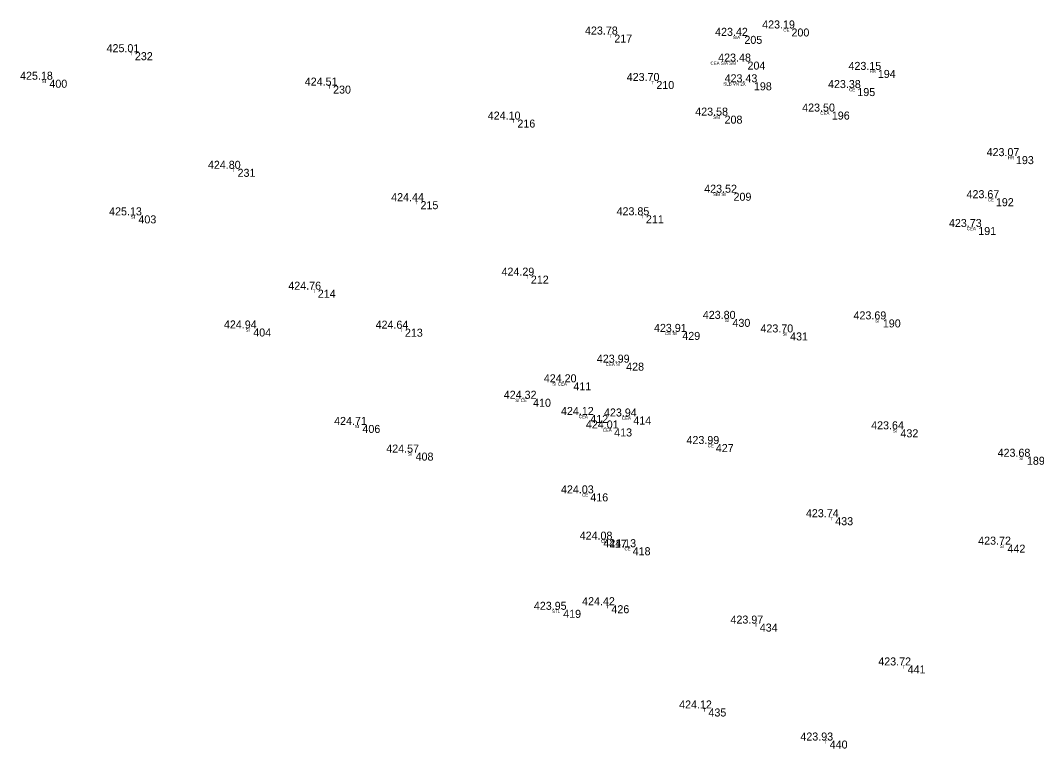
# Model space of a CAD drawing. Extents: x -639373 to -639057, y -1138651 to -1138359.
# Drawn here: x -639278.6 to -639183.3, y -1138568.9 to -1138500.7 of the extents above; entities that cross this region are included whole.
import ezdxf

# ---------------------------------------------------------------- set-up
doc = ezdxf.new("R2010")
doc.units = 0
for name, color, linetype in [('Vrstva 11', 7, 'Continuous'), ('Vrstva 13', 7, 'Continuous'), ('Vrstva 14', 7, 'Continuous'), ('Vrstva 57', 7, 'Continuous')]:
    doc.layers.add(name, color=color, linetype=linetype)

msp = doc.modelspace()

# ---------------------------------------------------------------- linework, layer by layer
at = {"layer": 'Vrstva 11'}
for p, q in [((-639223.19, -1138502.05), (-639223.19, -1138502.05)), ((-639211, -1138502.17), (-639211, -1138502.17)), ((-639206.59, -1138501.48), (-639206.59, -1138501.48)), ((-639268.11, -1138503.7), (-639268.11, -1138503.7)), ((-639210.71, -1138504.58), (-639210.71, -1138504.58)), ((-639198.5, -1138505.36), (-639198.5, -1138505.36)), ((-639276.12, -1138506.28), (-639276.12, -1138506.28)), ((-639249.54, -1138506.83), (-639249.54, -1138506.83)), ((-639219.25, -1138506.4), (-639219.25, -1138506.4)), ((-639210.11, -1138506.52), (-639210.11, -1138506.52)), ((-639200.42, -1138507.06), (-639200.42, -1138507.06)), ((-639232.27, -1138510.01), (-639232.27, -1138510.01)), ((-639212.86, -1138509.64), (-639212.86, -1138509.64)), ((-639202.81, -1138509.26), (-639202.81, -1138509.26)), ((-639185.56, -1138513.43), (-639185.56, -1138513.43)), ((-639258.49, -1138514.62), (-639258.49, -1138514.62)), ((-639241.35, -1138517.65), (-639241.35, -1138517.65)), ((-639212.02, -1138516.86), (-639212.02, -1138516.86)), ((-639187.44, -1138517.37), (-639187.44, -1138517.37)), ((-639267.78, -1138518.98), (-639267.78, -1138518.98)), ((-639220.23, -1138518.97), (-639220.23, -1138518.97)), ((-639189.09, -1138520.07), (-639189.09, -1138520.07)), ((-639231.01, -1138524.62), (-639231.01, -1138524.62)), ((-639250.97, -1138525.94), (-639250.97, -1138525.94)), ((-639212.12, -1138528.67), (-639212.12, -1138528.67)), ((-639198.03, -1138528.72), (-639198.03, -1138528.72)), ((-639257.02, -1138529.57), (-639257.02, -1138529.57)), ((-639242.81, -1138529.59), (-639242.81, -1138529.59)), ((-639216.82, -1138529.89), (-639216.82, -1138529.89)), ((-639206.72, -1138529.94), (-639206.72, -1138529.94)), ((-639222.08, -1138532.77), (-639222.08, -1138532.77)), ((-639227.02, -1138534.61), (-639227.02, -1138534.61)), ((-639230.8, -1138536.15), (-639230.8, -1138536.15)), ((-639246.79, -1138538.6), (-639246.79, -1138538.6)), ((-639225.44, -1138537.67), (-639225.44, -1138537.67)), ((-639221.41, -1138537.81), (-639221.41, -1138537.81)), ((-639223.2, -1138538.93), (-639223.2, -1138538.93)), ((-639196.38, -1138539.01), (-639196.38, -1138539.01)), ((-639213.68, -1138540.39), (-639213.68, -1138540.39)), ((-639241.81, -1138541.19), (-639241.81, -1138541.19)), ((-639184.53, -1138541.58), (-639184.53, -1138541.58)), ((-639225.44, -1138545.01), (-639225.44, -1138545.01)), ((-639202.49, -1138547.24), (-639202.49, -1138547.24)), ((-639223.69, -1138549.34), (-639223.69, -1138549.34)), ((-639186.35, -1138549.81), (-639186.35, -1138549.81)), ((-639221.47, -1138550.05), (-639221.47, -1138550.05)), ((-639223.46, -1138555.48), (-639223.46, -1138555.48)), ((-639227.98, -1138555.91), (-639227.98, -1138555.91)), ((-639209.56, -1138557.2), (-639209.56, -1138557.2)), ((-639195.71, -1138561.12), (-639195.71, -1138561.12)), ((-639214.37, -1138565.15), (-639214.37, -1138565.15)), ((-639203.01, -1138568.15), (-639203.01, -1138568.15))]:
    msp.add_line(p, q, dxfattribs=at)

# ---------------------------------------------------------------- texts
at = {"layer": 'Vrstva 13'}
for s, p in [(' 200', (-639206.59, -1138502.23)), (' 217', (-639223.19, -1138502.8)), (' 205', (-639211, -1138502.92)), (' 232', (-639268.11, -1138504.45)), (' 204', (-639210.71, -1138505.33)), (' 194', (-639198.5, -1138506.11)), (' 400', (-639276.12, -1138507.03)), (' 230', (-639249.54, -1138507.58)), (' 210', (-639219.25, -1138507.15)), (' 198', (-639210.11, -1138507.27)), (' 195', (-639200.42, -1138507.81)), (' 216', (-639232.27, -1138510.76)), (' 208', (-639212.86, -1138510.39)), (' 196', (-639202.81, -1138510.01)), (' 193', (-639185.56, -1138514.18)), (' 231', (-639258.49, -1138515.37)), (' 215', (-639241.35, -1138518.4)), (' 209', (-639212.02, -1138517.61)), (' 192', (-639187.44, -1138518.12)), (' 403', (-639267.78, -1138519.73)), (' 211', (-639220.23, -1138519.72)), (' 191', (-639189.09, -1138520.82)), (' 212', (-639231.01, -1138525.37)), (' 214', (-639250.97, -1138526.69)), (' 430', (-639212.12, -1138529.42)), (' 190', (-639198.03, -1138529.47)), (' 404', (-639257.02, -1138530.32)), (' 213', (-639242.81, -1138530.34)), (' 429', (-639216.82, -1138530.64)), (' 431', (-639206.72, -1138530.69)), (' 428', (-639222.08, -1138533.52)), (' 411', (-639227.02, -1138535.36)), (' 410', (-639230.8, -1138536.9)), (' 412', (-639225.44, -1138538.42)), (' 406', (-639246.79, -1138539.35)), (' 414', (-639221.41, -1138538.56)), (' 413', (-639223.2, -1138539.68)), (' 432', (-639196.38, -1138539.76)), (' 427', (-639213.68, -1138541.14)), (' 408', (-639241.81, -1138541.94)), (' 189', (-639184.53, -1138542.33)), (' 416', (-639225.44, -1138545.76)), (' 433', (-639202.49, -1138547.99)), (' 417', (-639223.69, -1138550.09)), (' 418', (-639221.47, -1138550.8)), (' 442', (-639186.35, -1138550.56)), (' 426', (-639223.46, -1138556.23)), (' 419', (-639227.98, -1138556.66)), (' 434', (-639209.56, -1138557.95)), (' 441', (-639195.71, -1138561.87)), (' 435', (-639214.37, -1138565.9)), (' 440', (-639203.01, -1138568.9))]:
    msp.add_text(s, height=0.75, dxfattribs=at).set_placement(p)
at = {"layer": 'Vrstva 14'}
for s, p in [('423.78 ', (-639225.659, -1138502.05)), ('423.42 ', (-639213.469, -1138502.17)), ('423.19 ', (-639209.059, -1138501.48)), ('425.01 ', (-639270.485, -1138503.7)), ('423.48 ', (-639213.179, -1138504.58)), ('423.15 ', (-639200.97, -1138505.36)), ('425.18 ', (-639278.589, -1138506.28)), ('424.51 ', (-639251.915, -1138506.83)), ('423.70 ', (-639221.749, -1138506.4)), ('423.43 ', (-639212.579, -1138506.52)), ('423.38 ', (-639202.889, -1138507.06)), ('423.58 ', (-639215.329, -1138509.64)), ('423.50 ', (-639205.309, -1138509.26)), ('424.10 ', (-639234.769, -1138510.01)), ('423.07 ', (-639188.029, -1138513.43)), ('424.80 ', (-639260.989, -1138514.62)), ('423.52 ', (-639214.489, -1138516.86)), ('423.67 ', (-639189.909, -1138517.37)), ('424.44 ', (-639243.819, -1138517.65)), ('425.13 ', (-639270.249, -1138518.98)), ('423.85 ', (-639222.7, -1138518.97)), ('423.73 ', (-639191.559, -1138520.07)), ('424.29 ', (-639233.479, -1138524.62)), ('424.76 ', (-639253.456, -1138525.94)), ('423.80 ', (-639214.619, -1138528.67)), ('423.69 ', (-639200.499, -1138528.72)), ('424.94 ', (-639259.489, -1138529.57)), ('424.64 ', (-639245.279, -1138529.59)), ('423.91 ', (-639219.195, -1138529.89)), ('423.70 ', (-639209.219, -1138529.94)), ('423.99 ', (-639224.549, -1138532.77)), ('424.20 ', (-639229.519, -1138534.61)), ('424.32 ', (-639233.269, -1138536.15)), ('424.12 ', (-639227.909, -1138537.67)), ('423.94 ', (-639223.879, -1138537.81)), ('424.71 ', (-639249.165, -1138538.6)), ('424.01 ', (-639225.575, -1138538.93)), ('423.64 ', (-639198.849, -1138539.01)), ('424.57 ', (-639244.279, -1138541.19)), ('423.99 ', (-639216.149, -1138540.39)), ('423.68 ', (-639186.999, -1138541.58)), ('424.03 ', (-639227.909, -1138545.01)), ('423.74 ', (-639204.959, -1138547.24)), ('424.08 ', (-639226.159, -1138549.34)), ('423.72 ', (-639188.819, -1138549.81)), ('424.13 ', (-639223.939, -1138550.05)), ('424.42 ', (-639225.929, -1138555.48)), ('423.95 ', (-639230.45, -1138555.91)), ('423.97 ', (-639212.029, -1138557.2)), ('423.72 ', (-639198.179, -1138561.12)), ('424.12 ', (-639216.839, -1138565.15)), ('423.93 ', (-639205.479, -1138568.15))]:
    msp.add_text(s, height=0.75, dxfattribs=at).set_placement(p)
at = {"layer": 'Vrstva 57'}
for s, p in [('CE', (-639207.078, -1138501.78)), ('T', (-639223.39, -1138502.35)), ('SIA', (-639211.8, -1138502.47)), ('T', (-639268.31, -1138504)), ('CEA SIA SIB', (-639213.899, -1138504.88)), ('HR', (-639198.989, -1138505.66)), ('SI', (-639276.558, -1138506.58)), ('T', (-639249.74, -1138507.13)), ('T', (-639219.45, -1138506.7)), ('SLB VN 2X', (-639212.698, -1138506.82)), ('CE', (-639200.907, -1138507.36)), ('T', (-639232.47, -1138510.31)), ('SIB', (-639213.649, -1138509.94)), ('CEA', (-639203.61, -1138509.56)), ('HR', (-639186.049, -1138513.73)), ('T', (-639258.69, -1138514.92)), ('T', (-639241.55, -1138517.95)), ('SIB SI', (-639213.658, -1138517.16)), ('CE', (-639187.927, -1138517.67)), ('SI', (-639268.218, -1138519.28)), ('T', (-639220.43, -1138519.27)), ('CEA', (-639189.89, -1138520.37)), ('T', (-639231.21, -1138524.92)), ('T', (-639251.17, -1138526.24)), ('SI', (-639212.558, -1138528.97)), ('SI', (-639198.468, -1138529.02)), ('SI', (-639257.458, -1138529.87)), ('T', (-639243.01, -1138529.89)), ('CE SI', (-639218.158, -1138530.19)), ('SI', (-639207.158, -1138530.24)), ('CEA SI', (-639223.718, -1138533.07)), ('SI CEA', (-639228.72, -1138534.91)), ('SI CE', (-639232.188, -1138536.45)), ('SI', (-639247.228, -1138538.9)), ('CEA', (-639226.24, -1138537.97)), ('CEA', (-639222.21, -1138538.11)), ('CEA', (-639224, -1138539.23)), ('SI', (-639196.818, -1138539.31)), ('CE', (-639214.167, -1138540.69)), ('SI', (-639242.248, -1138541.49)), ('SI', (-639184.968, -1138541.88)), ('CE', (-639225.927, -1138545.31)), ('T', (-639202.69, -1138547.54)), ('CE', (-639224.177, -1138549.64)), ('SI', (-639186.788, -1138550.11)), ('CE', (-639221.958, -1138550.35)), ('T', (-639223.66, -1138555.78)), ('STL', (-639228.755, -1138556.21)), ('T', (-639209.76, -1138557.5)), ('T', (-639195.91, -1138561.42)), ('T', (-639214.57, -1138565.45)), ('T', (-639203.21, -1138568.45))]:
    msp.add_text(s, height=0.3, dxfattribs=at).set_placement(p)

doc.saveas('drawing.dxf')
